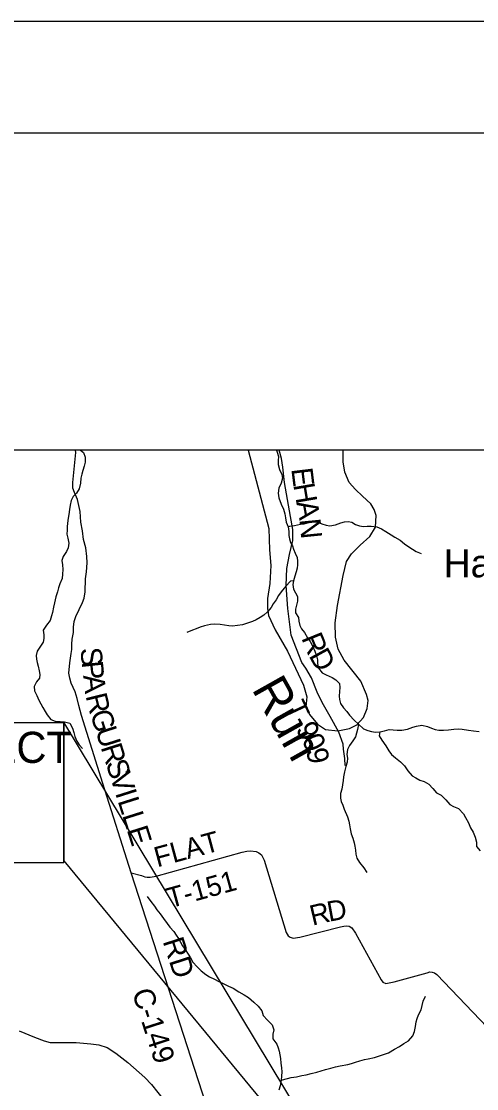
# Model space of a CAD drawing. Extents: x -139 to 835, y 0 to 440.
# Drawn here: x 127.4 to 168.3, y 344.1 to 440 of the extents above; entities that cross this region are included whole.
import ezdxf

# ---------------------------------------------------------------- set-up
doc = ezdxf.new("R2010")
doc.units = 0
for name, color, linetype in [('GM_X_County_Road', 7, 'Continuous'), ('GM_X_County_Road_Text', 7, 'Continuous'), ('GM_X_County_Text', 7, 'Continuous'), ('GM_X_Minor_River', 7, 'Continuous'), ('GM_X_Minor_River_Text', 7, 'Continuous'), ('GM_X_Rail_Line', 7, 'Continuous'), ('GM_X_Township_Road', 7, 'Continuous'), ('GM_X_Township_Road_Text', 7, 'Continuous'), ('GM_X_Unincorporated_Text', 7, 'Continuous'), ('SH_Border', 7, 'Continuous'), ('SH_Cut_Line', 7, 'Continuous'), ('SH_Text', 7, 'Continuous')]:
    doc.layers.add(name, color=color, linetype=linetype)

msp = doc.modelspace()

# ---------------------------------------------------------------- linework, layer by layer
at = {"layer": 'GM_X_County_Road'}
for points in [[(144.641, 340.684), (137.254, 363.525), (134.7, 371.562), (132.793, 377.659), (132.53, 378.549), (132.399, 379.193), (132.202, 379.767), (131.848, 380.563), (131.723, 381.013), (131.648, 381.45), (131.742, 382.378), (131.847, 383.22), (131.922, 383.593), (131.912, 384.052), (131.953, 384.522), (132.062, 385.111), (132.052, 385.594), (132.107, 386.112), (132.274, 386.554), (132.863, 387.817), (133.015, 388.2), (133.11, 388.777), (133.123, 389.936), (133.233, 390.561), (133.297, 391.356), (133.266, 391.949), (133.177, 392.725), (132.973, 393.468), (132.859, 394.233), (132.733, 395.022), (132.65, 395.979), (132.553, 396.513), (132.406, 397.061), (132.135, 397.673), (132.008, 398.064), (132.013, 398.595), (132.254, 401.27), (132.241, 401.486)], [(127.165, 349.341), (128.555, 348.774), (129.422, 348.448), (129.974, 348.292), (130.692, 348.278), (132.306, 348.292), (133.606, 348.179), (134.338, 348.066), (135.085, 347.825), (135.877, 347.329), (136.934, 346.483), (138.465, 345.135), (139.086, 344.52), (139.652, 343.787), (140.507, 342.714), (141.169, 342.177), (141.597, 341.903), (142.466, 341.523), (143.321, 341.196), (144.011, 340.921), (144.641, 340.684)]]:
    msp.add_lwpolyline(points, dxfattribs=at)
at = {"layer": 'GM_X_County_Text'}
msp.add_lwpolyline([(205.139, 401.486), (87.298, 401.486), (90.116, 391.109), (100.145, 354.177), (105.67, 333.828), (158.444, 330.1), (160.688, 329.921), (171.559, 329.033), (172.321, 330.669), (184.767, 357.384), (185.383, 358.364), (185.729, 359.048), (185.902, 359.821), (186.018, 360.334), (186.292, 360.95), (186.616, 361.275), (187.014, 361.689), (203.078, 396.689), (203.294, 397.153), (203.246, 397.371), (203.278, 397.973), (203.623, 399.152)], close=True, dxfattribs=at)
at = {"layer": 'GM_X_Minor_River'}
for points in [[(132.703, 401.486), (132.955, 401.272), (133.102, 400.861), (133.097, 400.402), (133.029, 400.041), (132.91, 399.669), (132.804, 399.32), (132.724, 398.972), (132.681, 398.526), (132.573, 398.009), (132.327, 397.626), (132.032, 397.315), (131.837, 396.956), (131.756, 396.547), (131.714, 396.161), (131.645, 395.716), (131.577, 395.367), (131.521, 394.922), (131.504, 394.608), (131.475, 394.307), (131.471, 393.945), (131.542, 393.583), (131.625, 393.136), (131.57, 392.727), (131.439, 392.378), (131.116, 391.948), (131.01, 391.563), (131.056, 391.177), (131.114, 390.766), (131.084, 390.345), (131.028, 389.959), (130.845, 389.491), (130.701, 389.107), (130.608, 388.77), (130.476, 388.314), (130.355, 387.785), (130.249, 387.376), (130.167, 386.918), (130.087, 386.594), (129.968, 386.197), (129.633, 385.779), (129.336, 385.312), (129.382, 384.914), (129.39, 384.576), (129.323, 384.227), (129.026, 383.784), (128.806, 383.425), (128.713, 383.052), (128.747, 382.726), (128.793, 382.412), (128.878, 382.086), (128.962, 381.663), (129.021, 381.325), (128.992, 381.023), (128.747, 380.689), (128.526, 380.257), (128.559, 379.859), (128.757, 379.459), (128.954, 379.046), (129.128, 378.707), (129.301, 378.379)], [(150.323, 401.486), (150.38, 401.318), (150.476, 400.931), (150.446, 400.557), (150.454, 400.208), (150.575, 399.736), (150.798, 399.287), (150.857, 398.973), (150.725, 398.528), (150.53, 398.085), (150.473, 397.615), (150.506, 397.192), (150.727, 396.635), (150.937, 396.175), (151.046, 395.776), (151.13, 395.413), (151.188, 395.026), (151.348, 394.615), (151.406, 394.18), (151.402, 393.83), (151.474, 393.516), (151.571, 393.201), (151.732, 392.886), (151.83, 392.584), (151.978, 392.244), (152.163, 391.832), (152.197, 391.53), (152.205, 391.193), (152.176, 390.892), (152.084, 390.567), (151.965, 390.159), (151.846, 389.762), (151.778, 389.425), (151.849, 389.014), (152.01, 388.687), (152.183, 388.335), (152.203, 387.925), (152.11, 387.552), (152.016, 387.192), (152.012, 386.866), (152.299, 386.465), (152.307, 386.127), (152.404, 385.752), (152.565, 385.437), (152.84, 385.096), (153.1, 384.623), (153.337, 384.307), (153.51, 383.98), (153.769, 383.434), (153.903, 383.023), (154, 382.648), (154.009, 382.322), (154.093, 381.911), (154.417, 381.498), (154.769, 381.313), (155.298, 381.054), (155.651, 380.845), (155.964, 380.54), (156.01, 380.166), (155.967, 379.804), (155.937, 379.383), (155.958, 379.081), (156.068, 378.742), (156.342, 378.353), (156.642, 378), (156.866, 377.684), (157.279, 377.245), (157.692, 376.867), (158.131, 376.464), (158.509, 376.315), (158.863, 376.215), (159.217, 376.163), (159.584, 376.183), (160.016, 376.286), (160.423, 376.402), (160.791, 376.374), (161.158, 376.334), (161.563, 376.329), (162.071, 376.432), (162.568, 376.619), (162.886, 376.712), (163.368, 376.779), (163.873, 376.665)], [(151.348, 394.615), (151.514, 394.673), (151.92, 394.729), (152.466, 394.831), (152.783, 394.876), (153.101, 394.957), (153.533, 395.036), (154.014, 395.007), (154.38, 394.882), (154.784, 394.745), (155.112, 394.681), (155.608, 394.772), (156.079, 394.947), (156.41, 395.052), (156.765, 395.072), (157.093, 395.008), (157.42, 394.824), (157.761, 394.699), (158.115, 394.635), (158.457, 394.655), (158.825, 394.663), (159.318, 394.598), (159.734, 394.424), (160.15, 394.178), (160.615, 393.896), (160.954, 393.675), (161.42, 393.404), (161.821, 393.074), (162.211, 392.817), (162.538, 392.608), (162.864, 392.387), (163.306, 392.213)], [(151.846, 389.762), (151.553, 389.717), (151.155, 389.263), (150.718, 388.774), (150.486, 388.439), (150.291, 388.043), (150.008, 387.672), (149.839, 387.361), (149.505, 386.955), (149.171, 386.669), (148.852, 386.456), (148.495, 386.255), (148.151, 386.09), (147.603, 385.915), (147.26, 385.81), (146.816, 385.743), (146.359, 385.688), (146.017, 385.704), (145.625, 385.756), (145.258, 385.821), (144.777, 385.862), (144.371, 385.831), (143.838, 385.716), (143.443, 385.588), (143.074, 385.447), (142.756, 385.318), (142.259, 385.095)], [(129.301, 378.379), (129.512, 378.027), (129.698, 377.712), (130.023, 377.298), (130.414, 377.161), (130.857, 377.12), (131.249, 377.08), (131.729, 376.954), (131.977, 376.529), (132.086, 376.142), (132.171, 375.779), (132.355, 375.343), (132.579, 375.027), (132.867, 374.698)], [(157.692, 376.867), (157.598, 376.398), (157.492, 376.073), (157.412, 375.749), (157.167, 375.378), (156.87, 374.947), (156.701, 374.611), (156.645, 374.166), (156.679, 373.828), (156.649, 373.466), (156.555, 373.07), (156.41, 372.601), (156.341, 372.156), (156.299, 371.831), (156.243, 371.421), (156.176, 371.048), (156.056, 370.64), (156.064, 370.242), (156.124, 369.94), (156.272, 369.6), (156.381, 369.25), (156.702, 368.547), (156.811, 368.16), (156.871, 367.821), (156.917, 367.483), (157.025, 367.024), (157.173, 366.648), (157.294, 366.213), (157.354, 365.911), (157.4, 365.549), (157.434, 365.199), (157.518, 364.848), (157.767, 364.46), (158.166, 363.973), (158.427, 363.548)], [(159.584, 376.183), (159.529, 375.821), (159.765, 375.433), (160.126, 374.935), (160.4, 374.485), (160.636, 374.145), (161, 373.84), (161.465, 373.497), (161.815, 373.131), (162.114, 372.694), (162.501, 372.231), (162.828, 372.047), (163.206, 371.862), (163.572, 371.725), (164.012, 371.491), (164.362, 371.113), (164.687, 370.7), (165.102, 370.502), (165.528, 370.075), (165.903, 369.649), (166.23, 369.476), (166.684, 369.291), (167.122, 368.815), (167.295, 368.488), (167.555, 368.027), (167.752, 367.578), (167.976, 367.166), (168.16, 366.718), (168.281, 366.282), (168.277, 365.897), (168.627, 365.507)], [(163.873, 376.665), (164.239, 376.516), (164.58, 376.392), (164.909, 376.352), (165.314, 376.335), (165.783, 376.354), (166.253, 376.421), (166.671, 376.453), (167.013, 376.437), (167.57, 376.346), (168.012, 376.281), (168.531, 376.227)], [(138.696, 361.407), (139.02, 360.957), (139.332, 360.543), (139.556, 360.215), (139.855, 359.838), (140.154, 359.413), (140.465, 358.963), (140.715, 358.659), (141.065, 358.245), (141.302, 357.929), (141.513, 357.625), (141.674, 357.286), (141.86, 356.971), (142.084, 356.63), (142.358, 356.23), (142.569, 355.878), (142.792, 355.513), (143.167, 355.087), (143.53, 354.721), (143.957, 354.379), (144.284, 354.195), (144.725, 353.973), (145.128, 353.775), (145.569, 353.565), (145.984, 353.356), (146.4, 353.158), (146.928, 352.851), (147.406, 352.556), (147.796, 352.323), (148.285, 351.919), (148.674, 351.553), (148.998, 351.14), (149.107, 350.717), (149.494, 350.29), (149.92, 349.864), (150.079, 349.428), (149.986, 349.031), (149.968, 348.609), (150.342, 348.123), (150.465, 347.82), (150.562, 347.494), (150.656, 346.841), (150.701, 346.443), (150.747, 346.009), (150.78, 345.647), (150.763, 345.249), (150.721, 344.912), (150.651, 344.406), (150.519, 344.01)], [(150.721, 344.912), (151.305, 345.05), (151.636, 345.143), (152.106, 345.21), (152.588, 345.325), (152.982, 345.393), (153.414, 345.497), (153.935, 345.623), (154.317, 345.74), (154.724, 345.856), (155.194, 345.995), (155.601, 346.111), (156.046, 346.178), (156.706, 346.315), (157.05, 346.408), (157.418, 346.524), (157.787, 346.641), (158.22, 346.769), (158.537, 346.825), (159.109, 346.939), (159.579, 347.079), (159.923, 347.207), (160.369, 347.371), (160.93, 347.678), (161.377, 347.927), (161.747, 348.188), (162.181, 348.448), (162.554, 348.878), (162.724, 349.286), (162.805, 349.719), (162.874, 350.14), (162.941, 350.453), (163.072, 350.765), (163.305, 351.22), (163.399, 351.605), (163.48, 352.002), (163.688, 352.457)]]:
    msp.add_lwpolyline(points, dxfattribs=at)
at = {"layer": 'GM_X_Rail_Line'}
msp.add_lwpolyline([(147.75, 401.486), (149.623, 394.446), (149.675, 392.529), (149.784, 391.132), (149.702, 389.503), (149.511, 388.157), (149.511, 387.278), (149.582, 386.641), (150.176, 385.361), (151.283, 383.432), (152.733, 380.365), (153.03, 379.319), (152.945, 378.426), (153.272, 377.753), (153.983, 376.877), (154.717, 376.411), (155.825, 376.268), (156.857, 376.492), (157.517, 376.831), (158.122, 377.462), (158.464, 378.274), (158.563, 378.999), (158.409, 379.54), (157.9, 380.739), (156.395, 382.635), (155.856, 383.623), (155.618, 384.69), (155.591, 385.984), (155.782, 387.536), (156.3, 390.227), (156.613, 391.476), (157.051, 392.169), (157.827, 392.962), (158.699, 393.719), (159.222, 394.571), (159.267, 395.618), (159.086, 396.143), (158.774, 396.678), (158.039, 397.356), (157.414, 397.939), (156.835, 398.593), (156.463, 399.519), (156.3, 400.446), (156.3, 401.486)], dxfattribs=at)
at = {"layer": 'GM_X_Township_Road'}
for points in [[(156.485, 373.16), (156.443, 373.789), (156.344, 374.638), (156.295, 375.074), (155.912, 376.173), (155.12, 377.562), (154.399, 378.815), (153.973, 379.758), (153.469, 381.042), (152.939, 381.903), (152.6, 382.409), (151.614, 384.866), (151.325, 387.267), (151.165, 389.338), (151.228, 390.846), (151.473, 392.12), (151.769, 393.379), (151.776, 394.358), (151.573, 395.524), (151.014, 398.585), (150.869, 399.967), (150.755, 400.731), (150.543, 401.486)], [(137.254, 363.525), (138.16, 363.28), (138.474, 363.174), (138.689, 363.144), (138.943, 363.136), (139.48, 363.229), (147.222, 365.366), (147.632, 365.474), (147.976, 365.488), (148.482, 365.449), (148.732, 365.321), (148.967, 365.133), (149.205, 364.654), (151.188, 358.169), (151.356, 357.874), (151.543, 357.747), (151.82, 357.667), (152.407, 357.758), (156.057, 358.664), (156.351, 358.727), (156.619, 358.756), (156.846, 358.725), (157.083, 358.585), (157.411, 358.116), (159.723, 353.904), (159.881, 353.694), (160.144, 353.577), (160.873, 353.749), (163.847, 354.554), (164.078, 354.62), (164.306, 354.601), (164.507, 354.546), (164.718, 354.383), (172.478, 346.266)]]:
    msp.add_lwpolyline(points, dxfattribs=at)
at = {"layer": 'SH_Border'}
msp.add_lwpolyline([(30, 430), (670, 430), (670, 10), (30, 10)], close=True, dxfattribs=at)
at = {"layer": 'SH_Cut_Line'}
for points in [[(0, 0), (680, 0), (680, 440), (0, 440)], [(295.458, 319.381), (295.458, 401.486), (67.578, 401.486), (67.578, 336.518), (92.493, 334.759), (105.67, 333.828), (158.444, 330.1), (160.688, 329.921), (171.559, 329.033), (177.155, 328.576), (194.287, 327.176), (207.436, 326.102), (228.151, 324.569), (267.909, 321.538)]]:
    msp.add_lwpolyline(points, close=True, dxfattribs=at)
at = {"layer": 'SH_Text'}
for points in [[(131.202, 377.001), (104.926, 377.001), (104.926, 364.463), (131.202, 364.463)], [(159.052, 330.859), (131.176, 377.048), (131.176, 364.607)]]:
    msp.add_lwpolyline(points, close=True, dxfattribs=at)

# ---------------------------------------------------------------- texts
at = {"layer": 'GM_X_County_Road_Text'}
for s, height, rotation, p in [('S', 1.904, 276.12101, (132.659, 383.677)), ('P', 1.904, 276.13237, (132.789, 382.465)), ('A', 1.904, 276.30162, (132.92, 381.247)), ('R', 1.903, 283.76474, (133.137, 379.426)), ('G', 1.901, 287.61401, (133.525, 377.859)), ('U', 1.901, 287.54474, (134.008, 376.338)), ('R', 1.901, 287.54607, (134.489, 374.816)), ('S', 1.901, 287.54473, (134.938, 373.396)), ('V', 1.901, 287.54583, (135.307, 372.229)), ('I', 1.901, 287.54685, (135.788, 370.707)), ('L', 1.901, 287.54723, (136.013, 369.996)), ('L', 1.901, 287.54229, (136.422, 368.703)), ('E', 1.901, 287.54461, (136.831, 367.409)), ('RD', 1.9013, 287.90083, (140.058, 357.383)), ('C-149', 1.9013, 287.9133, (137.295, 352.813))]:
    msp.add_text(s, height=height, rotation=rotation, dxfattribs=at).set_placement(p)
at = {"layer": 'GM_X_Minor_River_Text'}
msp.add_text('Run', height=3.1581, rotation=299.27677, dxfattribs=at).set_placement((148.037, 380.041))
at = {"layer": 'GM_X_Township_Road_Text'}
for s, height, rotation, p in [('E', 1.904, 277.01716, (151.635, 399.806)), ('H', 1.903, 279.83258, (151.813, 398.373)), ('A', 1.903, 279.96565, (152.086, 396.801)), ('N', 1.904, 275.61455, (152.357, 395.268)), ('R', 1.9, 292.09083, (152.519, 384.619)), ('D', 1.895, 298.87873, (153.177, 383.033)), ('T', 1.898, 294.99581, (150.975, 378.466)), ('9', 1.894, 299.66641, (151.99, 376.436)), ('-', 1.895, 299.29498, (151.616, 377.102)), ('0', 1.898, 295.46176, (152.532, 375.488)), ('9', 1.903, 279.56325, (152.976, 374.596)), ('FLAT', 1.818, 15.12387, (139.589, 364.007)), ('T-151', 1.8184, 15.41781, (140.739, 360.336)), ('R', 1.816, 13.56574, (153.543, 358.768)), ('D', 1.812, 10.49476, (155.031, 359.128))]:
    msp.add_text(s, height=height, rotation=rotation, dxfattribs=at).set_placement(p)
at = {"layer": 'GM_X_Unincorporated_Text'}
msp.add_text('Harris', height=2.5099, rotation=0.00001, dxfattribs=at).set_placement((165.341, 390.065))
at = {"layer": 'SH_Text'}
msp.add_text('END PROJECT', height=2.79999, dxfattribs=at).set_placement((105.496, 373.395))

doc.saveas('drawing.dxf')
